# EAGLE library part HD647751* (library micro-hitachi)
SH7751 Hitachi SuperH RISC engine The SH7751 Series microprocessor, featuring a built-in PCI bus controller compatible with PCs and multimedia devices. Source: Hitachi, Ltd. SH7751_R_V3.0.pdf
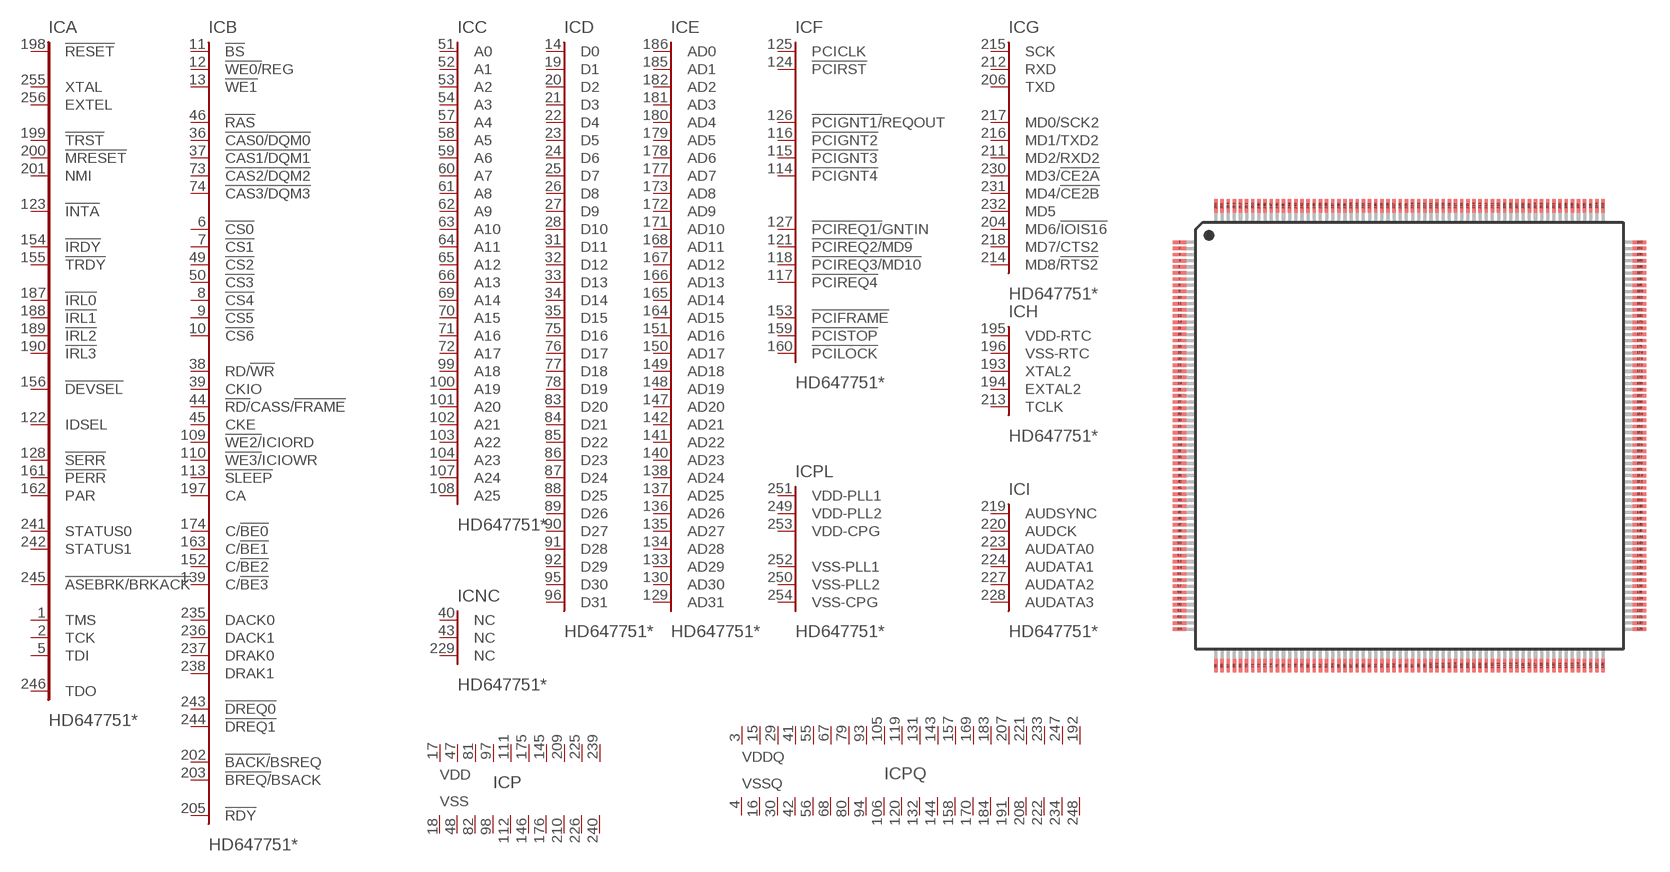
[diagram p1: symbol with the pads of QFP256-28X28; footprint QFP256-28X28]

Designator prefix IC; gates A=SH7751-S C=SH7751-A D=SH7751-D E=SH7751-AD G=SH7751-SER H=SH7751-RTC I=SH7751-AU P=SH7751-PWR PQ=SH7751-PWRQ_Q PL=SH7751-PLL NC=SH7751-NCQ B=SH7751-CONTROL F=SH7751-PCI

## HD647751F167 (OC_FARNELL: unknown; OC_NEWARK: unknown), HD647751RF200 (OC_FARNELL: unknown; OC_NEWARK: unknown), HD647751RF240 (OC_FARNELL: unknown; OC_NEWARK: unknown)  [QFP256-28X28]
1  A:TMS  in
2  A:TCK  in
3  PQ:VDDQ  pwr
4  PQ:VSSQ  pwr
5  A:TDI  in
6  B:!CS0  out
7  B:!CS1  out
8  B:!CS4  out
9  B:!CS5  out
10  B:!CS6  out
11  B:!BS  out
12  B:!WE0/!REG  out
13  B:!WE1  out
14  D:D0
15  PQ:VDDQ  pwr
16  PQ:VSSQ  pwr
17  P:VDD  pwr
18  P:VSS  pwr
19  D:D1
20  D:D2
21  D:D3
22  D:D4
23  D:D5
24  D:D6
25  D:D7
26  D:D8
27  D:D9
28  D:D10
29  PQ:VDDQ  pwr
30  PQ:VSSQ  pwr
31  D:D11
32  D:D12
33  D:D13
34  D:D14
35  D:D15
36  B:!CAS0/DQM0  out
37  B:!CAS1/DQM1  out
38  B:RD/!WR  out
39  B:CKIO  out
40  NC:NC  nc
41  PQ:VDDQ  pwr
42  PQ:VSSQ  pwr
43  NC:NC  nc
44  B:!RD/!CASS/!FRAME  out
45  B:CKE  out
46  B:!RAS  out
47  P:VDD  pwr
48  P:VSS  pwr
49  B:!CS2  out
50  B:!CS3  out
51  C:A0  out
52  C:A1  out
53  C:A2  out
54  C:A3  out
55  PQ:VDDQ  pwr
56  PQ:VSSQ  pwr
57  C:A4  out
58  C:A5  out
59  C:A6  out
60  C:A7  out
61  C:A8  out
62  C:A9  out
63  C:A10  out
64  C:A11  out
65  C:A12  out
66  C:A13  out
67  PQ:VDDQ  pwr
68  PQ:VSSQ  pwr
69  C:A14  out
70  C:A15  out
71  C:A16  out
72  C:A17  out
73  B:!CAS2/DQM2  out
74  B:!CAS3/DQM3  out
75  D:D16
76  D:D17
77  D:D18
78  D:D19
79  PQ:VDDQ  pwr
80  PQ:VSSQ  pwr
81  P:VDD  pwr
82  P:VSS  pwr
83  D:D20
84  D:D21
85  D:D22
86  D:D23
87  D:D24
88  D:D25
89  D:D26
90  D:D27
91  D:D28
92  D:D29
93  PQ:VDDQ  pwr
94  PQ:VSSQ  pwr
95  D:D30
96  D:D31
97  P:VDD  pwr
98  P:VSS  pwr
99  C:A18  out
100  C:A19  out
101  C:A20  out
102  C:A21  out
103  C:A22  out
104  C:A23  out
105  PQ:VDDQ  pwr
106  PQ:VSSQ  pwr
107  C:A24  out
108  C:A25  out
109  B:!WE2/!ICIORD  out
110  B:!WE3/!ICIOWR  out
111  P:VDD  pwr
112  P:VSS  pwr
113  B:!SLEEP  in
114  F:!PCIGNT4  out
115  F:!PCIGNT3  out
116  F:!PCIGNT2  out
117  F:!PCIREQ4  in
118  F:!PCIREQ3/MD10  in
119  PQ:VDDQ  pwr
120  PQ:VSSQ  pwr
121  F:!PCIREQ2/MD9  in
122  A:IDSEL  in
123  A:!INTA  out
124  F:!PCIRST  out
125  F:PCICLK  in
126  F:!PCIGNT1/!REQOUT  out
127  F:!PCIREQ1/!GNTIN  in
128  A:!SERR
129  E:AD31
130  E:AD30
131  PQ:VDDQ  pwr
132  PQ:VSSQ  pwr
133  E:AD29
134  E:AD28
135  E:AD27
136  E:AD26
137  E:AD25
138  E:AD24
139  B:C/!BE3
140  E:AD23
141  E:AD22
142  E:AD21
143  PQ:VDDQ  pwr
144  PQ:VSSQ  pwr
145  P:VDD  pwr
146  P:VSS  pwr
147  E:AD20
148  E:AD19
149  E:AD18
150  E:AD17
151  E:AD16
152  B:C/!BE2
153  F:!PCIFRAME
154  A:!IRDY
155  A:!TRDY
156  A:!DEVSEL
157  PQ:VDDQ  pwr
158  PQ:VSSQ  pwr
159  F:!PCISTOP
160  F:!PCILOCK
161  A:!PERR
162  A:PAR
163  B:C/!BE1
164  E:AD15
165  E:AD14
166  E:AD13
167  E:AD12
168  E:AD11
169  PQ:VDDQ  pwr
170  PQ:VSSQ  pwr
171  E:AD10
172  E:AD9
173  E:AD8
174  B:C/!BE0
175  P:VDD  pwr
176  P:VSS  pwr
177  E:AD7
178  E:AD6
179  E:AD5
180  E:AD4
181  E:AD3
182  E:AD2
183  PQ:VDDQ  pwr
184  PQ:VSSQ  pwr
185  E:AD1
186  E:AD0
187  A:!IRL0  in
188  A:!IRL1  in
189  A:!IRL2  in
190  A:!IRL3  in
191  PQ:VSSQ  pwr
192  PQ:VDDQ  pwr
193  H:XTAL2  out
194  H:EXTAL2  in
195  H:VDD-RTC  pwr
196  H:VSS-RTC  pwr
197  B:CA  in
198  A:!RESET  in
199  A:!TRST  in
200  A:!MRESET  in
201  A:NMI  in
202  B:!BACK/!BSREQ  out
203  B:!BREQ/!BSACK  in
204  G:MD6/!IOIS16  in
205  B:!RDY  in
206  G:TXD  out
207  PQ:VDDQ  pwr
208  PQ:VSSQ  pwr
209  P:VDD  pwr
210  P:VSS  pwr
211  G:MD2/RXD2  in
212  G:RXD  in
213  H:TCLK
214  G:MD8/!RTS2
215  G:SCK
216  G:MD1/TXD2
217  G:MD0/SCK2
218  G:MD7/CTS2
219  I:AUDSYNC  pas
220  I:AUDCK  pas
221  PQ:VDDQ  pwr
222  PQ:VSSQ  pwr
223  I:AUDATA0  pas
224  I:AUDATA1  pas
225  P:VDD  pwr
226  P:VSS  pwr
227  I:AUDATA2  pas
228  I:AUDATA3  pas
229  NC:NC  nc
230  G:MD3/!CE2A
231  G:MD4/!CE2B
232  G:MD5  in
233  PQ:VDDQ  pwr
234  PQ:VSSQ  pwr
235  B:DACK0  out
236  B:DACK1  out
237  B:DRAK0  out
238  B:DRAK1  out
239  P:VDD  pwr
240  P:VSS  pwr
241  A:STATUS0  out
242  A:STATUS1  out
243  B:!DREQ0  in
244  B:!DREQ1  in
245  A:!ASEBRK/BRKACK
246  A:TDO  out
247  PQ:VDDQ  pwr
248  PQ:VSSQ  pwr
249  PL:VDD-PLL2  pwr
250  PL:VSS-PLL2  pwr
251  PL:VDD-PLL1  pwr
252  PL:VSS-PLL1  pwr
253  PL:VDD-CPG  pwr
254  PL:VSS-CPG  pwr
255  A:XTAL  out
256  A:EXTEL  in

## Footprint QFP256-28X28 (pad centres in mm)
256-pin QFP Hitachi Code FP-256G Source: SH7751_R_V3.0.pdf
smd 0.9 x 0.22: 1 -14.975,12.6; 2 -14.975,12.2; 3 -14.975,11.8; 4 -14.975,11.4; 5 -14.975,11; 6 -14.975,10.6; 7 -14.975,10.2; 8 -14.975,9.8; 9 -14.975,9.4; 10 -14.975,9; 11 -14.975,8.6; 12 -14.975,8.2; 13 -14.975,7.8; 14 -14.975,7.4; 15 -14.975,7; 16 -14.975,6.6; 17 -14.975,6.2; 18 -14.975,5.8; 19 -14.975,5.4; 20 -14.975,5; 21 -14.975,4.6; 22 -14.975,4.2; 23 -14.975,3.8; 24 -14.975,3.4; 25 -14.975,3; 26 -14.975,2.6; 27 -14.975,2.2; 28 -14.975,1.8; 29 -14.975,1.4; 30 -14.975,1; 31 -14.975,0.6; 32 -14.975,0.2; 33 -14.975,-0.2; 34 -14.975,-0.6; 35 -14.975,-1; 36 -14.975,-1.4; 37 -14.975,-1.8; 38 -14.975,-2.2; 39 -14.975,-2.6; 40 -14.975,-3; 41 -14.975,-3.4; 42 -14.975,-3.8; 43 -14.975,-4.2; 44 -14.975,-4.6; 45 -14.975,-5; 46 -14.975,-5.4; 47 -14.975,-5.8; 48 -14.975,-6.2; 49 -14.975,-6.6; 50 -14.975,-7; 51 -14.975,-7.4; 52 -14.975,-7.8; 53 -14.975,-8.2; 54 -14.975,-8.6; 55 -14.975,-9; 56 -14.975,-9.4; 57 -14.975,-9.8; 58 -14.975,-10.2; 59 -14.975,-10.6; 60 -14.975,-11; 61 -14.975,-11.4; 62 -14.975,-11.8; 63 -14.975,-12.2; 64 -14.975,-12.6; 129 14.975,-12.6; 130 14.975,-12.2; 131 14.975,-11.8; 132 14.975,-11.4; 133 14.975,-11; 134 14.975,-10.6; 135 14.975,-10.2; 136 14.975,-9.8; 137 14.975,-9.4; 138 14.975,-9; 139 14.975,-8.6; 140 14.975,-8.2; 141 14.975,-7.8; 142 14.975,-7.4; 143 14.975,-7; 144 14.975,-6.6; 145 14.975,-6.2; 146 14.975,-5.8; 147 14.975,-5.4; 148 14.975,-5; 149 14.975,-4.6; 150 14.975,-4.2; 151 14.975,-3.8; 152 14.975,-3.4; 153 14.975,-3; 154 14.975,-2.6; 155 14.975,-2.2; 156 14.975,-1.8; 157 14.975,-1.4; 158 14.975,-1; 159 14.975,-0.6; 160 14.975,-0.2; 161 14.975,0.2; 162 14.975,0.6; 163 14.975,1; 164 14.975,1.4; 165 14.975,1.8; 166 14.975,2.2; 167 14.975,2.6; 168 14.975,3; 169 14.975,3.4; 170 14.975,3.8; 171 14.975,4.2; 172 14.975,4.6; 173 14.975,5; 174 14.975,5.4; 175 14.975,5.8; 176 14.975,6.2; 177 14.975,6.6; 178 14.975,7; 179 14.975,7.4; 180 14.975,7.8; 181 14.975,8.2; 182 14.975,8.6; 183 14.975,9; 184 14.975,9.4; 185 14.975,9.8; 186 14.975,10.2; 187 14.975,10.6; 188 14.975,11; 189 14.975,11.4; 190 14.975,11.8; 191 14.975,12.2; 192 14.975,12.6
smd 0.22 x 0.9: 65 -12.6,-14.975; 66 -12.2,-14.975; 67 -11.8,-14.975; 68 -11.4,-14.975; 69 -11,-14.975; 70 -10.6,-14.975; 71 -10.2,-14.975; 72 -9.8,-14.975; 73 -9.4,-14.975; 74 -9,-14.975; 75 -8.6,-14.975; 76 -8.2,-14.975; 77 -7.8,-14.975; 78 -7.4,-14.975; 79 -7,-14.975; 80 -6.6,-14.975; 81 -6.2,-14.975; 82 -5.8,-14.975; 83 -5.4,-14.975; 84 -5,-14.975; 85 -4.6,-14.975; 86 -4.2,-14.975; 87 -3.8,-14.975; 88 -3.4,-14.975; 89 -3,-14.975; 90 -2.6,-14.975; 91 -2.2,-14.975; 92 -1.8,-14.975; 93 -1.4,-14.975; 94 -1,-14.975; 95 -0.6,-14.975; 96 -0.2,-14.975; 97 0.2,-14.975; 98 0.6,-14.975; 99 1,-14.975; 100 1.4,-14.975; 101 1.8,-14.975; 102 2.2,-14.975; 103 2.6,-14.975; 104 3,-14.975; 105 3.4,-14.975; 106 3.8,-14.975; 107 4.2,-14.975; 108 4.6,-14.975; 109 5,-14.975; 110 5.4,-14.975; 111 5.8,-14.975; 112 6.2,-14.975; 113 6.6,-14.975; 114 7,-14.975; 115 7.4,-14.975; 116 7.8,-14.975; 117 8.2,-14.975; 118 8.6,-14.975; 119 9,-14.975; 120 9.4,-14.975; 121 9.8,-14.975; 122 10.2,-14.975; 123 10.6,-14.975; 124 11,-14.975; 125 11.4,-14.975; 126 11.8,-14.975; 127 12.2,-14.975; 128 12.6,-14.975; 193 12.6,14.975; 194 12.2,14.975; 195 11.8,14.975; 196 11.4,14.975; 197 11,14.975; 198 10.6,14.975; 199 10.2,14.975; 200 9.8,14.975; 201 9.4,14.975; 202 9,14.975; 203 8.6,14.975; 204 8.2,14.975; 205 7.8,14.975; 206 7.4,14.975; 207 7,14.975; 208 6.6,14.975; 209 6.2,14.975; 210 5.8,14.975; 211 5.4,14.975; 212 5,14.975; 213 4.6,14.975; 214 4.2,14.975; 215 3.8,14.975; 216 3.4,14.975; 217 3,14.975; 218 2.6,14.975; 219 2.2,14.975; 220 1.8,14.975; 221 1.4,14.975; 222 1,14.975; 223 0.6,14.975; 224 0.2,14.975; 225 -0.2,14.975; 226 -0.6,14.975; 227 -1,14.975; 228 -1.4,14.975; 229 -1.8,14.975; 230 -2.2,14.975; 231 -2.6,14.975; 232 -3,14.975; 233 -3.4,14.975; 234 -3.8,14.975; 235 -4.2,14.975; 236 -4.6,14.975; 237 -5,14.975; 238 -5.4,14.975; 239 -5.8,14.975; 240 -6.2,14.975; 241 -6.6,14.975; 242 -7,14.975; 243 -7.4,14.975; 244 -7.8,14.975; 245 -8.2,14.975; 246 -8.6,14.975; 247 -9,14.975; 248 -9.4,14.975; 249 -9.8,14.975; 250 -10.2,14.975; 251 -10.6,14.975; 252 -11,14.975; 253 -11.4,14.975; 254 -11.8,14.975; 255 -12.2,14.975; 256 -12.6,14.975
